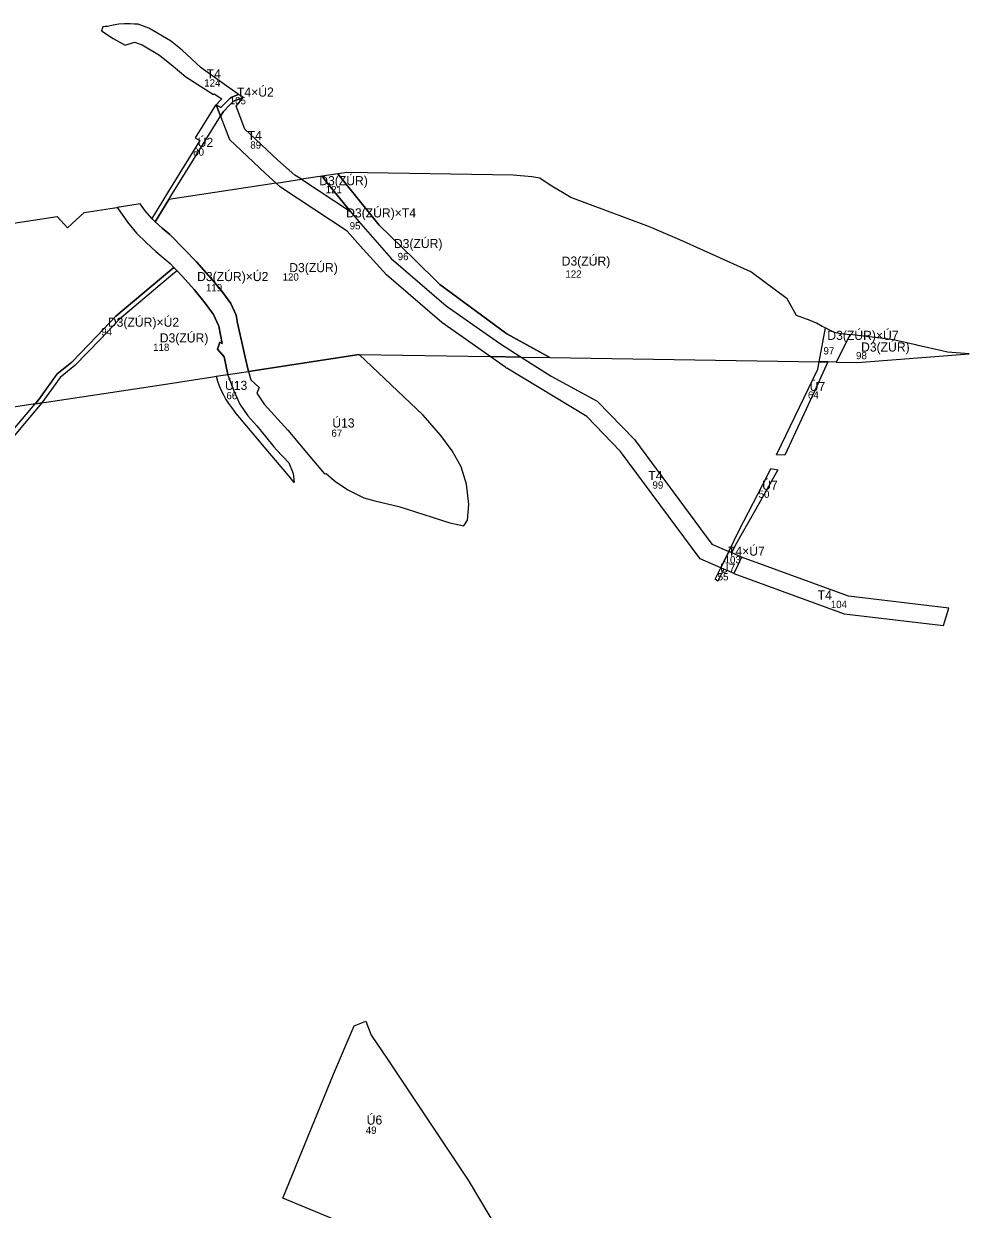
# Model space of a CAD drawing. Extents: x -521621 to -516857, y -1190025 to -1185894.
# Drawn here: x -518471 to -517431, y -1188636 to -1187332 of the extents above; entities that cross this region are included whole.
import ezdxf

# ---------------------------------------------------------------- set-up
doc = ezdxf.new("R2010")
doc.units = 0
for name, color, linetype in [('VPO_id', 7, 'Continuous'), ('VPO_n', 7, 'Continuous'), ('VPS_id', 7, 'Continuous'), ('VPS_n', 7, 'Continuous')]:
    doc.layers.add(name, color=color, linetype=linetype)

msp = doc.modelspace()

# ---------------------------------------------------------------- linework, layer by layer
at = {"layer": 'VPO_n'}
msp.add_line((-518259.3, -1187720.1), (-518251.5, -1187718.9), dxfattribs=at)
for points in [[(-518256.9, -1187428.3), (-518259.5, -1187421.5), (-518260.1, -1187422.1), (-518282.4, -1187458), (-518277.2, -1187460.9), (-518311.7, -1187516.6), (-518318, -1187526.7), (-518330.2, -1187546.5), (-518329.5, -1187547.4), (-518326.5, -1187550.1), (-518311.5, -1187525.7), (-518308.1, -1187520.3), (-518254.7, -1187434.1), (-518256.9, -1187428.3)], [(-517981.5, -1187861.2), (-517984, -1187838.7), (-517989.8, -1187819.8), (-517999.6, -1187802), (-518012.2, -1187785.1), (-518031.8, -1187762.8), (-518102, -1187696.1), (-518223.7, -1187714.7), (-518221.4, -1187724), (-518212.1, -1187732.3), (-518214.8, -1187738.7), (-518206.7, -1187750.6), (-518180.6, -1187779.3), (-518156.2, -1187808.2), (-518140.1, -1187827.4), (-518138.5, -1187827.1), (-518129.6, -1187834.7), (-518128.2, -1187835.9), (-518114.6, -1187845), (-518097.1, -1187853.8), (-518084.7, -1187856.9), (-518058.6, -1187863.4), (-518021.9, -1187875.1), (-518002.4, -1187881.3), (-517987, -1187884.5), (-517982.9, -1187878.1), (-517981.5, -1187861.2)], [(-518251.5, -1187718.9), (-518246.6, -1187718.2), (-518246.4, -1187718.8), (-518239.9, -1187736), (-518233.5, -1187750.6), (-518224.4, -1187763.4), (-518214.8, -1187774.7), (-518205.2, -1187786.3), (-518195.8, -1187797.6), (-518192.9, -1187801.1), (-518179.6, -1187815.4), (-518174.7, -1187826.8), (-518173.4, -1187836.7), (-518179.5, -1187829.5), (-518191.9, -1187814.8), (-518200.3, -1187804.9), (-518239.2, -1187758.9)], [(-517695.5, -1187912.6), (-517684.5, -1187890.1), (-517652.7, -1187828.4), (-517649.4, -1187821.4), (-517641.6, -1187823), (-517665.7, -1187866.1), (-517688.4, -1187906.2), (-517692.2, -1187914)], [(-517692.2, -1187914), (-517695.5, -1187912.6)], [(-517701, -1187932), (-517707.4, -1187945.2), (-517710.4, -1187943), (-517704.3, -1187930.6)], [(-517704.3, -1187930.6), (-517701, -1187932)]]:
    msp.add_lwpolyline(points, dxfattribs=at)
for points in [[(-517633.7, -1187806.7), (-517643.1, -1187806.5), (-517597.6, -1187712.2), (-517596.1, -1187704.1), (-517586.4, -1187704.3), (-517601.2, -1187736.4)], [(-518451.1, -1187749.3), (-518518.3, -1187828.7), (-518530, -1187850.3), (-518533.4, -1187846), (-518522.5, -1187825.9), (-518458.6, -1187750.5)], [(-518107.5, -1188434.2), (-518094.9, -1188429), (-518088.8, -1188444.4), (-518071, -1188471), (-517982, -1188604), (-517899.2, -1188742.7), (-518042.7, -1188683.1), (-518186.2, -1188623.6), (-518130.3, -1188487.5)]]:
    msp.add_lwpolyline(points, close=True, dxfattribs=at)
msp.add_arc((-518164.4, -1187695.6), 98, 194.4563, 220.234, dxfattribs=at)
at = {"layer": 'VPS_n'}
for points in [[(-518306.6, -1187379.1), (-518292.7, -1187390.8), (-518262.4, -1187410.1), (-518261.7, -1187409.4), (-518253.1, -1187414.9), (-518253.9, -1187415.7), (-518259.5, -1187421.5), (-518254.2, -1187424.6), (-518248.7, -1187419), (-518243.2, -1187413.5), (-518234.7, -1187410.2), (-518237.9, -1187407.9), (-518245, -1187402.9), (-518275.7, -1187381.1), (-518296.7, -1187361.5), (-518309.7, -1187351.1), (-518333.6, -1187337.4), (-518339.3, -1187335.3), (-518344.5, -1187333.3), (-518345, -1187333.1), (-518346.4, -1187333), (-518349.6, -1187332.8), (-518354.1, -1187332.4), (-518360.3, -1187332.7), (-518366.5, -1187332.9), (-518372.6, -1187334.2), (-518378.8, -1187335.5), (-518381.4, -1187335.6), (-518384, -1187335.7), (-518384.7, -1187338.1), (-518385, -1187339.1), (-518385.4, -1187340.4), (-518372.8, -1187348.8), (-518359.5, -1187355.9), (-518349.2, -1187352.8), (-518340.9, -1187355.7), (-518321.7, -1187367.1), (-518306.6, -1187379.1)], [(-518240.4, -1187417.7), (-518229.8, -1187413.7), (-518232.2, -1187411.9), (-518234.7, -1187410.2), (-518243.2, -1187413.5), (-518248.7, -1187419), (-518254.2, -1187424.6), (-518259.5, -1187421.5), (-518256.9, -1187428.3), (-518254.7, -1187434.1), (-518251.4, -1187428.9), (-518244.4, -1187421.8), (-518240.4, -1187417.7)], [(-518240.4, -1187417.7), (-518244.4, -1187421.8), (-518251.4, -1187428.9), (-518254.7, -1187434.1), (-518244.8, -1187459.6), (-518205.2, -1187497.2), (-518193.2, -1187507.7), (-518165.5, -1187503.5), (-518172.9, -1187498.9), (-518191.7, -1187482.4), (-518227.7, -1187448.2), (-518237.5, -1187423), (-518229.8, -1187413.7), (-518240.4, -1187417.7)], [(-518223.7, -1187714.7), (-518102, -1187696.1), (-517958.1, -1187698.4), (-518011.3, -1187661), (-518072.1, -1187608.7), (-518097.5, -1187580.5), (-518115.1, -1187560.4), (-518188.5, -1187512.3), (-518193.2, -1187507.7), (-518311.5, -1187525.7), (-518326.5, -1187550.1), (-518318.7, -1187557.1), (-518310.4, -1187564.3), (-518294.1, -1187580.8), (-518281, -1187594.4), (-518267.8, -1187609.4), (-518266.5, -1187610.8), (-518253.1, -1187626.6), (-518243.1, -1187639.9), (-518237.5, -1187652.9), (-518235.9, -1187661.6), (-518231.2, -1187682.4), (-518226.7, -1187702.5), (-518223.7, -1187714.7)], [(-518142.6, -1187500), (-518165.5, -1187503.5), (-518111.5, -1187538.9), (-518137.5, -1187507.1), (-518142.6, -1187500)], [(-518142.6, -1187500), (-518137.5, -1187507.1), (-518111.5, -1187538.9), (-518102.9, -1187549.4), (-518067, -1187590.4), (-518006.3, -1187642.7), (-517947.8, -1187683.7), (-517923.8, -1187698.9), (-517892.4, -1187699.4), (-517939.8, -1187673.3), (-518013.4, -1187619.1), (-518042.1, -1187591.1), (-518080.2, -1187553.9), (-518125.5, -1187497.4), (-518142.6, -1187500)], [(-517939.8, -1187673.3), (-517892.4, -1187699.4), (-517596.1, -1187704.1), (-517589.2, -1187666.9), (-517592.8, -1187665.3), (-517598.9, -1187661.5), (-517606, -1187658.8), (-517620.9, -1187653.2), (-517631.2, -1187635), (-517671.4, -1187605.2), (-517749.3, -1187570.2), (-517780, -1187556.7), (-517785.5, -1187554.6), (-517829, -1187538.4), (-517869.1, -1187523.4), (-517892, -1187510.1), (-517903.3, -1187502.1), (-517912.3, -1187500.7), (-517932.8, -1187498.8), (-518115.5, -1187495.9), (-518125.5, -1187497.4), (-518080.2, -1187553.9), (-518042.1, -1187591.1), (-518013.4, -1187619.1), (-517939.8, -1187673.3)], [(-518614.8, -1187572), (-518434.3, -1187544.5), (-518423, -1187557), (-518404.5, -1187539.9), (-518376.1, -1187535.6), (-518368.5, -1187534.4), (-518367.9, -1187534.7), (-518356.8, -1187550.6), (-518347, -1187562.8), (-518336.4, -1187572.9), (-518325.6, -1187582.7), (-518310, -1187596), (-518305.9, -1187600.4), (-518310.5, -1187604.3), (-518369.6, -1187653.8), (-518390.1, -1187675.7), (-518418.1, -1187704.4), (-518434.6, -1187717.9), (-518454.6, -1187745.7), (-518458.6, -1187750.5), (-518594.2, -1187771.1)], [(-518318.7, -1187557.1), (-518326.5, -1187550.1), (-518329.5, -1187547.4), (-518330.2, -1187546.5), (-518337.4, -1187538), (-518343, -1187530.5), (-518352.3, -1187532), (-518368.1, -1187534.4), (-518367.9, -1187534.7), (-518356.8, -1187550.6), (-518347, -1187562.8), (-518336.4, -1187572.9), (-518325.6, -1187582.7), (-518310, -1187596), (-518305.9, -1187600.4), (-518304.1, -1187602.2), (-518302.4, -1187604), (-518296.4, -1187610.4), (-518283.6, -1187624.5), (-518271.6, -1187639.8), (-518262.3, -1187652.3), (-518256.3, -1187664.8), (-518252.6, -1187684.1), (-518255.4, -1187682.6), (-518258, -1187690.3), (-518250.4, -1187698.8), (-518246.6, -1187718.2), (-518223.7, -1187714.7), (-518226.7, -1187702.5), (-518231.2, -1187682.4), (-518235.9, -1187661.6), (-518237.5, -1187652.9), (-518243.1, -1187639.9), (-518253.1, -1187626.6), (-518266.5, -1187610.8), (-518267.8, -1187609.4), (-518281, -1187594.4), (-518294.1, -1187580.8), (-518310.4, -1187564.3), (-518318.7, -1187557.1)], [(-518302.4, -1187604), (-518307, -1187607.8), (-518366.2, -1187657.5), (-518386.5, -1187679.2), (-518414.8, -1187708.1), (-518430.9, -1187721.3), (-518451.1, -1187749.3), (-518322.2, -1187729.7), (-518263.2, -1187720.7), (-518259.3, -1187720.1), (-518246.6, -1187718.2), (-518250.4, -1187698.8), (-518258, -1187690.3), (-518255.4, -1187682.6), (-518252.6, -1187684.1), (-518256.3, -1187664.8), (-518262.3, -1187652.3), (-518271.6, -1187639.8), (-518283.6, -1187624.5), (-518296.4, -1187610.4), (-518302.4, -1187604)], [(-517586.4, -1187704.3), (-517596.1, -1187704.1), (-517589.2, -1187666.9), (-517580.3, -1187671.2), (-517573, -1187672.9), (-517572.6, -1187673), (-517572, -1187673.1)], [(-517562, -1187674.2), (-517577.2, -1187704.4)], [(-517562, -1187674.2), (-517577.2, -1187704.4), (-517553.8, -1187704.8), (-517430.9, -1187695.3), (-517454.8, -1187693.5), (-517461.3, -1187692.1), (-517487.3, -1187686.2), (-517489.9, -1187685.6), (-517514.8, -1187680), (-517520.3, -1187679.3), (-517520.3, -1187679.3), (-517537.9, -1187676.9), (-517553.7, -1187675.1), (-517562, -1187674.2)], [(-517572, -1187673.1), (-517562, -1187674.2)], [(-517940.8, -1187710.5), (-517958.1, -1187698.4), (-517923.8, -1187698.9), (-517890.9, -1187719.9)], [(-517577.2, -1187704.4), (-517586.4, -1187704.3)], [(-517704.3, -1187930.6), (-517726.9, -1187920.7), (-517814.6, -1187802.6), (-517851.6, -1187764.3), (-517939.7, -1187711.3)], [(-517890.9, -1187719.9), (-517840.1, -1187747.4), (-517799.3, -1187789.7), (-517714, -1187904.5), (-517695.5, -1187912.6)], [(-517695.5, -1187912.6), (-517704.3, -1187930.6)], [(-517689.8, -1187936.9), (-517568.5, -1187981.4), (-517459.3, -1187994.2), (-517453.5, -1187975), (-517563.8, -1187961.9), (-517681.4, -1187918.8), (-517685.6, -1187927.8), (-517689.8, -1187936.9)]]:
    msp.add_lwpolyline(points, dxfattribs=at)
for points in [[(-518193.2, -1187507.7), (-518165.5, -1187503.5), (-518111.5, -1187538.9), (-518102.9, -1187549.4), (-518067, -1187590.4), (-518006.3, -1187642.7), (-517947.8, -1187683.7), (-517923.8, -1187698.9), (-517958.1, -1187698.4), (-518011.3, -1187661), (-518072.1, -1187608.7), (-518097.5, -1187580.5), (-518115.1, -1187560.4), (-518188.5, -1187512.3)], [(-518434.6, -1187717.9), (-518418.1, -1187704.4), (-518390.1, -1187675.7), (-518369.6, -1187653.8), (-518310.5, -1187604.3), (-518305.9, -1187600.4), (-518304.1, -1187602.2), (-518302.4, -1187604), (-518307, -1187607.8), (-518366.2, -1187657.5), (-518386.5, -1187679.2), (-518414.8, -1187708.1), (-518430.9, -1187721.3), (-518451.1, -1187749.3), (-518454.9, -1187749.9), (-518458.6, -1187750.5), (-518454.6, -1187745.7), (-518434.6, -1187718)], [(-517704.3, -1187930.6), (-517695.5, -1187912.6), (-517692.2, -1187914), (-517681.4, -1187918.8), (-517685.6, -1187927.8), (-517689.8, -1187936.9), (-517695.4, -1187934.5), (-517701, -1187932)]]:
    msp.add_lwpolyline(points, close=True, dxfattribs=at)
msp.add_arc((-517929.3, -1187694.1), 20, 234.944, 238.9499, dxfattribs=at)

# ---------------------------------------------------------------- texts
at = {"layer": 'VPO_id'}
for s, p in [('80', (-518284.6, -1187477.5)), ('66', (-518248.1, -1187745.3)), ('64', (-517608.4, -1187744.7)), ('67', (-518132.6, -1187786.6)), ('50', (-517662.7, -1187853.7)), ('55', (-517707.7, -1187944.5)), ('49', (-518094.8, -1188553))]:
    msp.add_text(s, height=8, dxfattribs=at).set_placement(p)
at = {"layer": 'VPO_n'}
for s, p in [('Ú2', (-518279.7, -1187467.9)), ('Ú13', (-518249.7, -1187735.1)), ('Ú7', (-517606.5, -1187736.3)), ('Ú13', (-518131.6, -1187776.4)), ('Ú7', (-517658.8, -1187844.9)), ('Ú7', (-517705.2, -1187936)), ('Ú6', (-518093.8, -1188542.8))]:
    msp.add_text(s, height=10, dxfattribs=at).set_placement(p)
at = {"layer": 'VPS_id'}
for s, p in [('124', (-518272.5, -1187401.5)), ('105', (-518244.5, -1187421)), ('89', (-518221.8, -1187469.8)), ('121', (-518138.9, -1187518.8)), ('95', (-518112.5, -1187558.6)), ('96', (-518059.7, -1187592.4)), ('120', (-518186.3, -1187614.9)), ('122', (-517875.2, -1187611.7)), ('119', (-518270.6, -1187626.7)), ('94', (-518385.8, -1187675)), ('118', (-518328.7, -1187692.2)), ('97', (-517591.3, -1187696.1)), ('98', (-517555.5, -1187701.3)), ('99', (-517779.4, -1187843.7)), ('103', (-517700.1, -1187925.8)), ('104', (-517583.3, -1187974.9))]:
    msp.add_text(s, height=8, dxfattribs=at).set_placement(p)
at = {"layer": 'VPS_n'}
for s, p in [('T4', (-518269.8, -1187392.5)), ('T4×Ú2', (-518236.5, -1187412.6)), ('T4', (-518224.7, -1187460.3)), ('D3(ZÚR)', (-518146, -1187510)), ('D3(ZÚR)×T4', (-518116.4, -1187545.4)), ('D3(ZÚR)', (-518063.9, -1187579.1)), ('D3(ZÚR)', (-517879.3, -1187598.4)), ('D3(ZÚR)', (-518179, -1187605.6)), ('D3(ZÚR)×Ú2', (-518280.3, -1187615.4)), ('D3(ZÚR)×Ú2', (-518378.5, -1187665.6)), ('D3(ZÚR)', (-518321.4, -1187682.9)), ('D3(ZÚR)×Ú7', (-517587.1, -1187680.1)), ('D3(ZÚR)', (-517550, -1187692.9)), ('T4', (-517784, -1187834.3)), ('T4×Ú7', (-517696.4, -1187917.3)), ('T4', (-517597.7, -1187965.6))]:
    msp.add_text(s, height=10, dxfattribs=at).set_placement(p)

doc.saveas('drawing.dxf')
